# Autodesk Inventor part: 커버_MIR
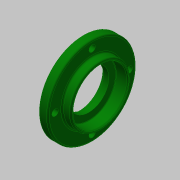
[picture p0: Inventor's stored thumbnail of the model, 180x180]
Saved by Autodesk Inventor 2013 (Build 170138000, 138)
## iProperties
Created: 2018-11
Part Number: 커버_MIR
Material: 알루미늄 6061
Document SubType Name: Modeling
Designer: Administrator
Density: 2.71 g/cm^3
Author: mduedu
d0: 62.000 mm
d2: 42.000 mm
d3: 40.000 mm
d4: 3.000 mm
d5: 6.000 mm
d6: 15.000 mm
d8: 38.000 mm
d10: 28.000 mm
d11: 33.000 mm
d12: 3.000 mm
d13: 8.300 mm
d15: 0.300 mm
d16: 0.800 mm
d18: 30.00 deg
d19: 1.000 mm
d20: 0.500 mm
d23: 52.000 mm
d24: 4.000 ul
d28: 4.500 mm
d26: 360.00 deg
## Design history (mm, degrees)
derived "커버.ipt"
  sketch "스케치1"
    geometry: L1 (0, 0)-(-3, 0) reference; L2 (-3, 0)-(-3, 20) reference; L3 (-3, 20)-(0, 20) reference; L4 (0, 20)-(0, 0) reference; L5 (-3, 0)-(-9, 0) reference; L6 (-9, 0)-(-9, 31) reference; L7 (-9, 31)-(-3, 31) reference; L8 (-3, 31)-(-3, 0) reference; L9 (-9, 0)-(-15, 0) reference; L10 (-15, 0)-(-15, 21) reference; L11 (-15, 21)-(-9, 21) reference; L12 (-9, 21)-(-9, 0) reference
  sketch "스케치2"
    geometry: L1 (0, -20)-(0, 20) reference; L2 (0, 20)-(-3, 20) reference; L3 (-3, 20)-(-3, 31) reference; L4 (-3, 31)-(-9, 31) reference; L5 (-9, 31)-(-9, 21) reference; L6 (-9, 21)-(-15, 21) reference; L7 (-15, 21)-(-15, -21) reference; L8 (-15, -21)-(-9, -21) reference; L9 (-9, -21)-(-9, -31) reference; L10 (-9, -31)-(-3, -31) reference; L11 (-3, -31)-(-3, -20) reference; L12 (-3, -20)-(0, -20) reference; L13 (0, 0)-(-3, 0) reference; L14 (-3, 0)-(-3, 16.5) reference; L15 (-3, 16.5)-(0, 16.5) reference; L16 (0, 16.5)-(0, 0) reference; L17 (-3, 0)-(-6.7, 0) reference; L18 (-6.7, 0)-(-6.7, 14) reference; L19 (-6.7, 14)-(-3, 14) reference; L20 (-3, 14)-(-3, 0) reference; L21 (-6.7, 0)-(-15, 0) reference; L22 (-15, 0)-(-15, 19) reference; L23 (-15, 19)-(-6.7, 19) reference; L24 (-6.7, 19)-(-6.7, 0) reference
  sketch "스케치3"
    geometry: 6 further points
    constraints: 1 vertical alignment, 1 other
  sketch "스케치4"
    geometry: 4 further points
feature "솔리드1::커버.ipt"
tag "피쳐 태그1"
node "솔리드1"
other parameters: "d0" = 10, "d0_1" = 62, "d2" = 42, "d3" = 40, "d4" = 3, "d5" = 6, "d6" = 15, "d8" = 38, "d10" = 28, "d11" = 33, "d12" = 3, "d13" = 8.3, "d15" = 0.3, "d16" = 0.8, "d18" = 30 deg, "d19" = 1, "d20" = 0.5, "d23" = 52, "d24" = 4, "d28" = 4.5, "d26" = 360 deg
